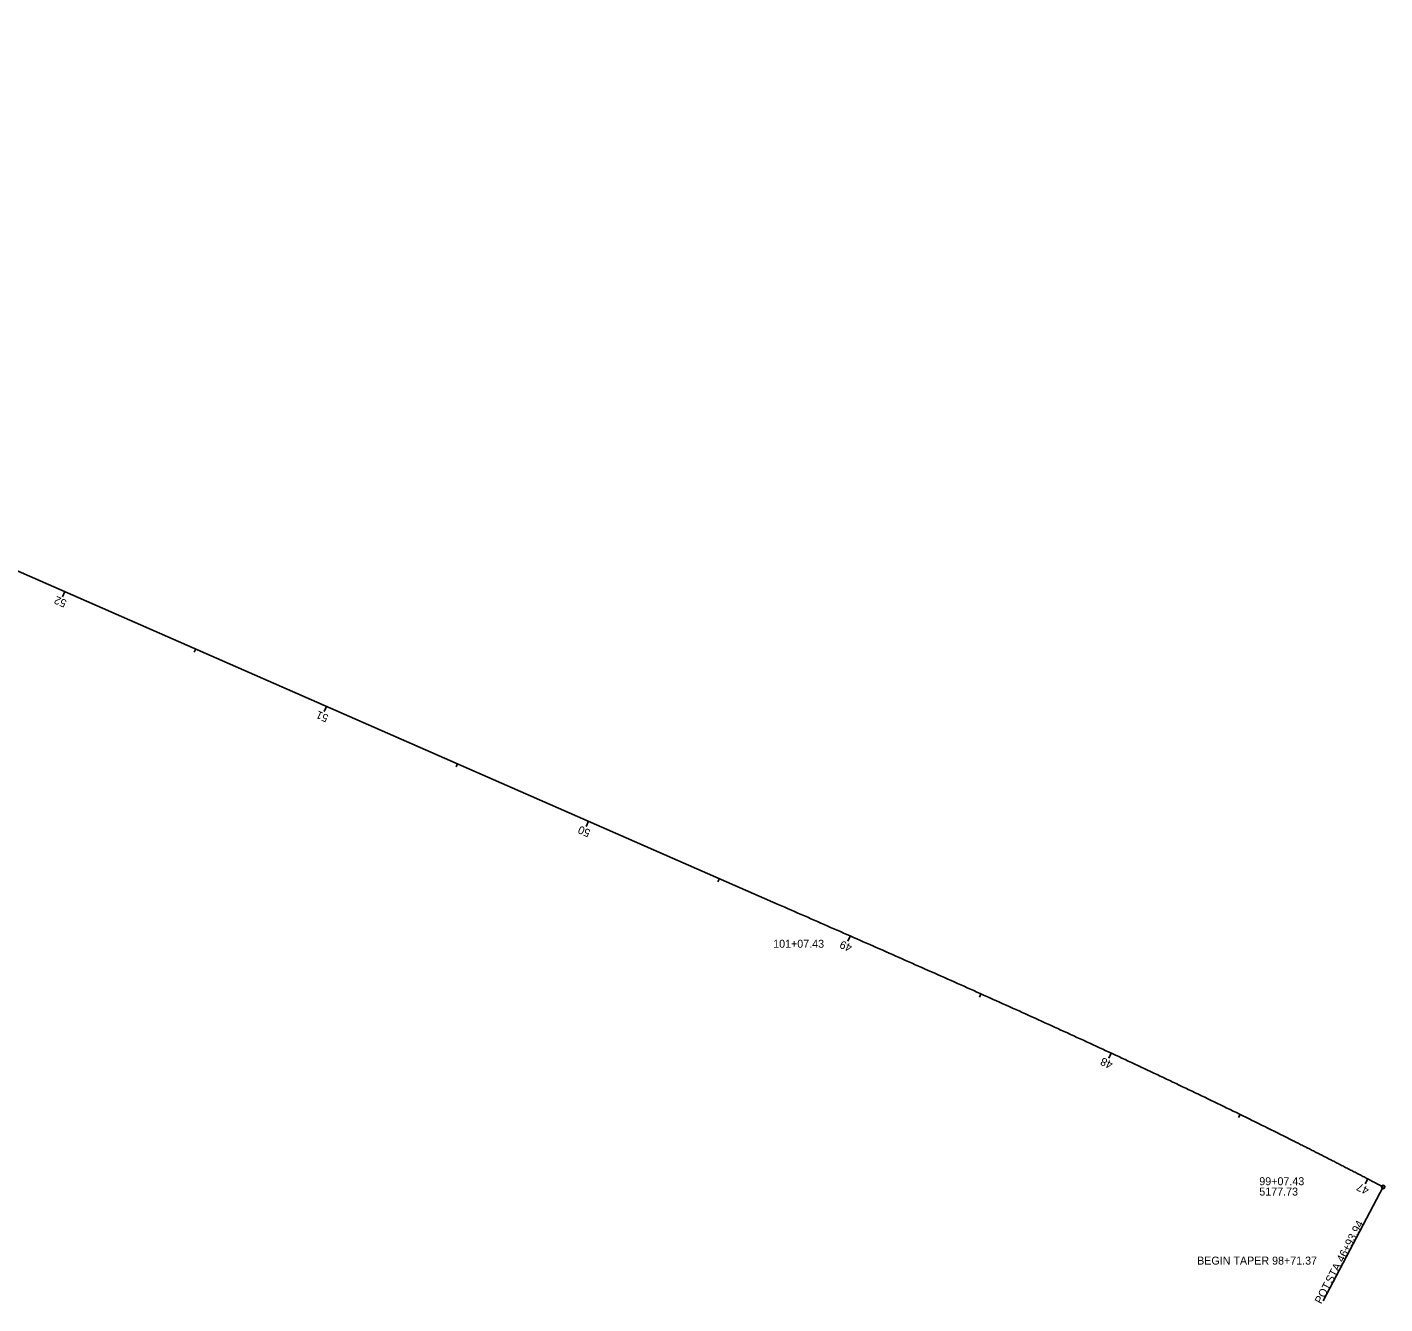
# Model space of a CAD drawing. Extents: x 1698884 to 1700452, y 716861 to 717517.
# Drawn here: x 1699977.1 to 1700452, y 716861.4 to 717307.9 of the extents above; entities that cross this region are included whole.
import ezdxf

# ---------------------------------------------------------------- set-up
doc = ezdxf.new("R2010")
doc.units = 0
for name, color, linetype in [('Default', 7, 'Continuous'), ('RS_Raster1', 7, 'Continuous'), ('RW_X_CL_100_Bearings', 7, 'Continuous'), ('RW_X_CL_100_Curve_Data', 7, 'Continuous'), ('RW_X_CL_100_Distances', 7, 'Continuous')]:
    doc.layers.add(name, color=color, linetype=linetype)

msp = doc.modelspace()

# ---------------------------------------------------------------- linework, layer by layer
at = {"layer": 'Default'}
for points in [[(1700419.94, 716918.45), (1700417.01, 716919.92), (1700411.15, 716922.85), (1700402.32, 716927.19), (1700393.47, 716931.49), (1700384.6, 716935.76), (1700375.7, 716940), (1700366.77, 716944.2), (1700357.83, 716948.38), (1700348.86, 716952.53), (1700339.86, 716956.65), (1700330.85, 716960.75), (1700321.82, 716964.84), (1700312.78, 716968.9), (1700303.71, 716972.95), (1700294.63, 716976.99), (1700285.54, 716981.02), (1700276.43, 716985.04), (1700267.3, 716989.06), (1700258.17, 716993.07), (1700249.02, 716997.08), (1700242.92, 716999.75), (1700239.87, 717001.09)], [(1700451.44, 716902.27), (1700450.92, 716902.55), (1700449.87, 716903.1), (1700448.3, 716903.92), (1700446.73, 716904.74), (1700445.16, 716905.56), (1700443.59, 716906.37), (1700442.02, 716907.19), (1700440.45, 716908), (1700438.87, 716908.82), (1700437.3, 716909.63), (1700435.72, 716910.44), (1700434.15, 716911.25), (1700432.57, 716912.05), (1700431, 716912.86), (1700429.42, 716913.66), (1700427.84, 716914.47), (1700426.26, 716915.27), (1700424.68, 716916.07), (1700423.1, 716916.86), (1700421.52, 716917.66), (1700420.46, 716918.19), (1700419.94, 716918.45)]]:
    msp.add_open_spline(points, degree=3, dxfattribs=at)
at = {"layer": 'RS_Raster1'}
msp.add_line((1700239.87, 717001.09), (1699539.98, 717307.89), dxfattribs=at)
at = {"layer": 'RW_X_CL_100_Bearings'}
msp.add_line((1700239.87, 717001.09), (1699539.98, 717307.89), dxfattribs=at)
for points in [[(1700419.94, 716918.45), (1700417.01, 716919.92), (1700411.15, 716922.85), (1700402.32, 716927.19), (1700393.47, 716931.49), (1700384.6, 716935.76), (1700375.7, 716940), (1700366.77, 716944.2), (1700357.83, 716948.38), (1700348.86, 716952.53), (1700339.86, 716956.65), (1700330.85, 716960.75), (1700321.82, 716964.84), (1700312.78, 716968.9), (1700303.71, 716972.95), (1700294.63, 716976.99), (1700285.54, 716981.02), (1700276.43, 716985.04), (1700267.3, 716989.06), (1700258.17, 716993.07), (1700249.02, 716997.08), (1700242.92, 716999.75), (1700239.87, 717001.09)], [(1700451.44, 716902.27), (1700450.92, 716902.55), (1700449.87, 716903.1), (1700448.3, 716903.92), (1700446.73, 716904.74), (1700445.16, 716905.56), (1700443.59, 716906.37), (1700442.02, 716907.19), (1700440.45, 716908), (1700438.87, 716908.82), (1700437.3, 716909.63), (1700435.72, 716910.44), (1700434.15, 716911.25), (1700432.57, 716912.05), (1700431, 716912.86), (1700429.42, 716913.66), (1700427.84, 716914.47), (1700426.26, 716915.27), (1700424.68, 716916.07), (1700423.1, 716916.86), (1700421.52, 716917.66), (1700420.46, 716918.19), (1700419.94, 716918.45)]]:
    msp.add_open_spline(points, degree=3, dxfattribs=at)
at = {"layer": 'RW_X_CL_100_Curve_Data'}
msp.add_line((1700451.44, 716902.27), (1700430.52, 716862.43), dxfattribs=at)
msp.add_circle((1700451.44, 716902.27), 0.6, dxfattribs=at)
at = {"layer": 'RW_X_CL_100_Distances'}
for p, q in [((1699990.3, 717110.49), (1699989.5, 717108.66)), ((1700036.09, 717090.42), (1700035.61, 717089.32)), ((1700081.89, 717070.34), (1700081.08, 717068.51)), ((1700127.68, 717050.27), (1700127.2, 717049.17)), ((1700173.47, 717030.2), (1700172.67, 717028.36)), ((1700219.27, 717010.12), (1700218.79, 717009.02)), ((1700265.06, 716990.04), (1700264.25, 716988.21)), ((1700310.78, 716969.8), (1700310.29, 716968.7)), ((1700356.28, 716949.09), (1700355.44, 716947.27)), ((1700401.44, 716927.61), (1700400.91, 716926.53)), ((1700446.07, 716905.08), (1700445.15, 716903.31))]:
    msp.add_line(p, q, dxfattribs=at)

# ---------------------------------------------------------------- texts
at = {"layer": 'RS_Raster1'}
for s, p in [('101+07.43', (1700238.09, 716985.93)), ('99+07.43', (1700408.13, 716902.88)), ('5177.73', (1700408.13, 716899.26)), ('BEGIN TAPER 98+71.37', (1700386.38, 716875.12))]:
    msp.add_text(s, height=2.8, dxfattribs=at).set_placement(p)
at = {"layer": 'RW_X_CL_100_Curve_Data'}
for s, p in [('46+93.94', (1700437.44, 716875.69)), (' STA. ', (1700433.1, 716867.44)), ('POT', (1700429.79, 716861.13))]:
    msp.add_text(s, height=2.8, rotation=62.2894, dxfattribs=at).set_placement(p)
at = {"layer": 'RW_X_CL_100_Distances'}
for s, rotation, p in [('52', 156.3296, (1699991.21, 717107.36)), ('51', 156.3296, (1700082.81, 717067.21)), ('50', 156.3296, (1700174.44, 717027.04)), ('49', 156.2767, (1700265.98, 716986.9)), ('48', 155.1132, (1700357.17, 716945.92)), ('47', 152.459, (1700446.8, 716901.88))]:
    msp.add_text(s, height=2.8, rotation=rotation, dxfattribs=at).set_placement(p)

doc.saveas('drawing.dxf')
